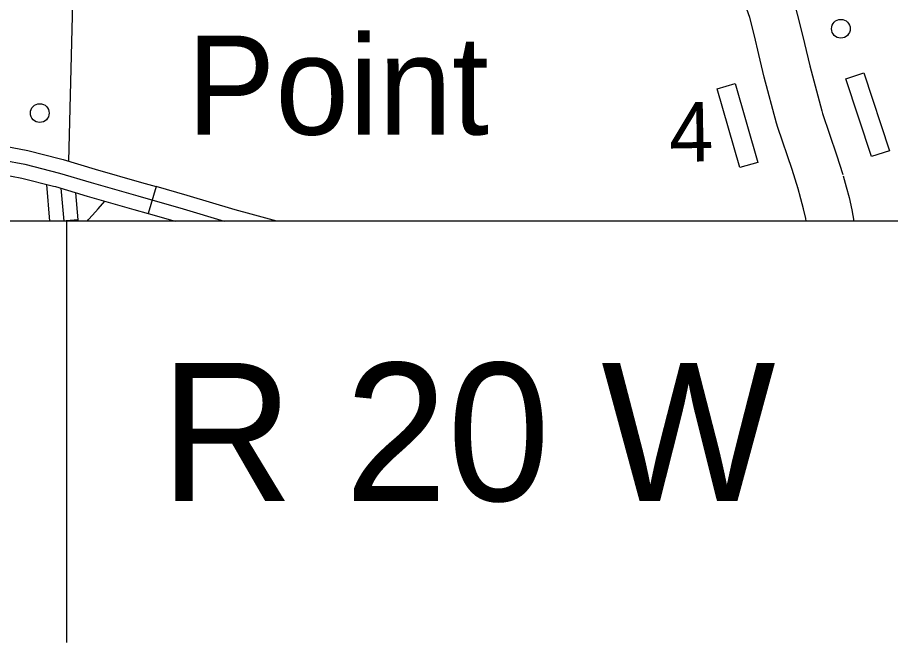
# Model space of a CAD drawing. Extents: x 1369979 to 1371646, y 379997 to 381064.
# Drawn here: x 1370912.7 to 1370967.2, y 380120.1 to 380159.1 of the extents above; entities that cross this region are included whole.
import ezdxf

# ---------------------------------------------------------------- set-up
doc = ezdxf.new("R2010")
doc.units = 0
for name, color, linetype in [('Default', 7, 'Continuous'), ('R_Border Notes', 7, 'Continuous'), ('R_No Plot', 7, 'Continuous')]:
    doc.layers.add(name, color=color, linetype=linetype)

msp = doc.modelspace()

# ---------------------------------------------------------------- linework, layer by layer
at = {"layer": 'R_Border Notes'}
for p, q in [((1370921.368, 380148.56), (1370920.886, 380146.87)), ((1370916.498, 380146.477), (1370915.509, 380146.391)), ((1370915.8, 380120.073), (1370915.8, 380146.391))]:
    msp.add_line(p, q, dxfattribs=at)
for points in [[(1370916.499, 380210.323), (1370916.415, 380170.909), (1370916.35, 380168.312), (1370915.894, 380150.153)], [(1370952.459, 380175.227), (1370952.991, 380174.797), (1370953.584, 380174.348), (1370954.026, 380173.934), (1370954.551, 380173.409), (1370955.014, 380172.891), (1370955.519, 380172.234), (1370955.887, 380171.696), (1370956.238, 380171.064), (1370956.879, 380169.88), (1370957.56, 380168.436), (1370958.134, 380167.178), (1370959.217, 380164.998), (1370959.692, 380163.958), (1370960.587, 380161.829), (1370961.242, 380159.97), (1370961.575, 380158.683), (1370961.861, 380157.49), (1370962.187, 380156.108), (1370962.931, 380153.295), (1370962.98, 380153.124), (1370963.859, 380150.543), (1370964.255, 380149.314)], [(1370961.467, 380148.416), (1370961.078, 380149.622), (1370960.183, 380152.249), (1370960.106, 380152.518), (1370959.344, 380155.397), (1370959.011, 380156.812), (1370958.732, 380157.975), (1370958.437, 380159.114), (1370957.852, 380160.774), (1370957.008, 380162.782), (1370956.572, 380163.738), (1370955.489, 380165.917), (1370954.902, 380167.203), (1370954.264, 380168.556), (1370953.669, 380169.656), (1370953.392, 380170.155), (1370953.147, 380170.513), (1370952.758, 380171.018), (1370952.421, 380171.396), (1370951.988, 380171.829), (1370951.693, 380172.106), (1370951.187, 380172.489), (1370950.62, 380172.946)], [(1370909.071, 380151.22), (1370909.152, 380151.222), (1370910.614, 380151.222), (1370911.947, 380151.083), (1370913.362, 380150.811), (1370915.402, 380150.294)], [(1370892.785, 380146.391), (1370892.984, 380146.54), (1370895.17, 380148.181), (1370896.393, 380149.067), (1370897.096, 380149.431), (1370897.85, 380149.77), (1370898.865, 380150.004), (1370900.062, 380150.187), (1370903.23, 380150.239), (1370905.078, 380150.239), (1370909.163, 380150.343), (1370910.569, 380150.343), (1370911.818, 380150.213), (1370913.171, 380149.952), (1370915.331, 380149.405), (1370917.309, 380148.806), (1370920.224, 380147.973), (1370923.053, 380147.165), (1370925.614, 380146.391)], [(1370915.402, 380150.294), (1370915.567, 380150.252), (1370917.558, 380149.649), (1370920.466, 380148.818), (1370921.368, 380148.56)], [(1370909.116, 380149.463), (1370909.175, 380149.464), (1370910.523, 380149.464), (1370911.689, 380149.343), (1370912.98, 380149.094), (1370914.97, 380148.59)], [(1370964.279, 380149.23), (1370964.455, 380148.549), (1370964.64, 380147.878), (1370964.815, 380147.116), (1370964.932, 380146.391)], [(1370914.741, 380146.391), (1370914.54, 380148.699)], [(1370914.97, 380148.59), (1370915.096, 380148.558), (1370917.061, 380147.963), (1370919.983, 380147.127), (1370920.886, 380146.87)], [(1370915.623, 380146.391), (1370915.444, 380148.453)], [(1370927.298, 380146.83), (1370926.315, 380147.098), (1370923.301, 380148.008), (1370921.368, 380148.56)], [(1370961.965, 380146.391), (1370961.938, 380146.555), (1370961.8, 380147.159), (1370961.624, 380147.793), (1370961.442, 380148.5)], [(1370916.498, 380146.477), (1370916.35, 380148.178)], [(1370917.081, 380146.391), (1370917.147, 380146.513), (1370917.398, 380146.764), (1370917.753, 380147.163), (1370918.172, 380147.645)], [(1370920.886, 380146.87), (1370922.561, 380146.391)], [(1370928.903, 380146.391), (1370927.298, 380146.83)], [(1370916.505, 380146.391), (1370916.498, 380146.477)]]:
    msp.add_lwpolyline(points, dxfattribs=at)
for points in [[(1370964.443, 380155.301), (1370965.556, 380155.666), (1370967.155, 380150.795), (1370966.041, 380150.429)], [(1370956.4, 380154.674), (1370957.526, 380154.998), (1370958.941, 380150.07), (1370957.815, 380149.747)]]:
    msp.add_lwpolyline(points, close=True, dxfattribs=at)
for centre in [(1370964.128, 380158.421), (1370914.108, 380153.153)]:
    msp.add_circle(centre, 0.586, dxfattribs=at)
at = {"layer": 'R_No Plot'}
msp.add_lwpolyline([(1370544.495, 380586.867), (1371140.383, 380586.867), (1371140.383, 380146.391), (1370544.495, 380146.391)], close=True, dxfattribs=at)

# ---------------------------------------------------------------- texts
at = {"layer": 'Default'}
msp.add_text('R 20 W', height=8.6181, dxfattribs=at).set_placement((1370921.625, 380128.923))
at = {"layer": 'R_Border Notes'}
msp.add_text('Point', height=6.1875, dxfattribs=at).set_placement((1370923.295, 380151.805))
msp.add_text('4', height=3.712, rotation=1.0061, dxfattribs=at).set_placement((1370953.432, 380150.094))

doc.saveas('drawing.dxf')
